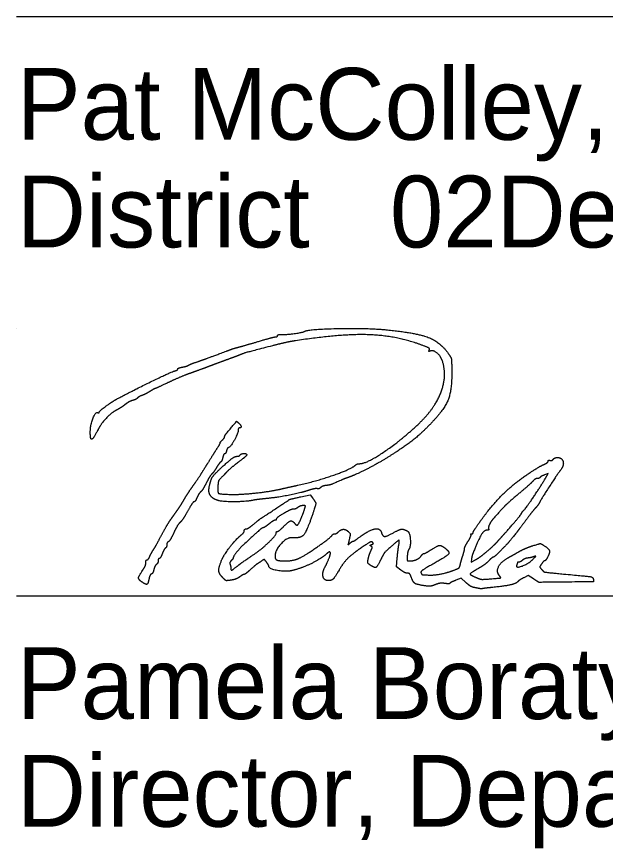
# Model space of a CAD drawing. Extents: x -8.3 to 42.1, y 0 to 22.
# Drawn here: x 24.528 to 25.676, y 7.305 to 8.926 of the extents above; entities that cross this region are included whole.
import ezdxf

# ---------------------------------------------------------------- set-up
doc = ezdxf.new("R2010")
doc.units = 0
doc.layers.add('SH_Data', color=7, linetype='Continuous')
doc.layers.add('SH_Text', color=7, linetype='Continuous')

msp = doc.modelspace()

# ---------------------------------------------------------------- linework, layer by layer
at = {"layer": 'SH_Data'}
for p, q in [((24.5279, 8.9262), (28.0279, 8.9262)), ((24.5279, 8.3191), (24.5279, 8.3191)), ((24.5279, 7.7968), (28.0279, 7.7968))]:
    msp.add_line(p, q, dxfattribs=at)
at = {"layer": 'SH_Text'}
for points in [[(25.5597, 8.0263), (25.5651, 8.0352), (25.5577, 8.0326)], [(25.0824, 7.9901), (25.1004, 7.9942), (25.1051, 7.988)], [(25.2773, 7.8473), (25.269, 7.8536), (25.2704, 7.8707)], [(25.4153, 7.8693), (25.4143, 7.8628), (25.4229, 7.8673)], [(25.5361, 7.83), (25.5255, 7.8368), (25.5171, 7.8323)], [(25.4043, 7.823), (25.3951, 7.8313), (25.3845, 7.8272)]]:
    msp.add_lwpolyline(points, dxfattribs=at)
for points in [[(25.033, 8.3018), (25.0351, 8.3018), (25.0368, 8.3029), (25.0368, 8.3043)], [(25.0368, 8.3043), (25.0368, 8.3056), (25.0408, 8.3066), (25.0458, 8.3065)], [(25.0458, 8.3065), (25.0554, 8.3062), (25.0864, 8.3106), (25.0898, 8.3127)], [(25.3205, 8.285), (25.2699, 8.304), (25.1619, 8.308), (25.0716, 8.2942)], [(25.0898, 8.3127), (25.0966, 8.3169), (25.2136, 8.3192), (25.248, 8.3158)], [(25.248, 8.3158), (25.3072, 8.31), (25.3548, 8.2917), (25.3706, 8.2686)], [(24.9612, 8.282), (24.9665, 8.2833), (24.9839, 8.2883), (25, 8.2931)], [(25, 8.2931), (25.0161, 8.2979), (25.031, 8.3018), (25.033, 8.3018)], [(25.0716, 8.2942), (25.0623, 8.2928), (25.0424, 8.2885), (25.0272, 8.2845)], [(24.8808, 8.2535), (24.8955, 8.2586), (24.9019, 8.261), (24.9372, 8.2741)], [(24.9372, 8.2741), (24.9451, 8.2771), (24.9559, 8.2806), (24.9612, 8.282)], [(25.0272, 8.2845), (24.9762, 8.2714), (24.9719, 8.2701), (24.9612, 8.2658)], [(25.3328, 8.2764), (25.3338, 8.2789), (25.3303, 8.2813), (25.3205, 8.285)], [(25.3352, 8.2743), (25.3326, 8.2733), (25.3319, 8.274), (25.3328, 8.2764)], [(25.3586, 8.2544), (25.3553, 8.2642), (25.3409, 8.2765), (25.3352, 8.2743)], [(24.9384, 8.2573), (24.9285, 8.2537), (24.9134, 8.2481), (24.9048, 8.2449)], [(24.9612, 8.2658), (24.9585, 8.2647), (24.9483, 8.2609), (24.9384, 8.2573)], [(25.3131, 8.1332), (25.344, 8.1627), (25.3679, 8.2262), (25.3586, 8.2544)], [(25.3706, 8.2686), (25.3755, 8.2614), (25.3764, 8.257), (25.3768, 8.2392)], [(24.837, 8.2357), (24.84, 8.2366), (24.8424, 8.2382), (24.8424, 8.2393)], [(24.8424, 8.2393), (24.8424, 8.2403), (24.8464, 8.242), (24.8514, 8.2429)], [(24.8514, 8.2429), (24.8563, 8.2438), (24.8615, 8.2454), (24.8628, 8.2464)], [(24.8628, 8.2464), (24.8641, 8.2473), (24.8722, 8.2506), (24.8808, 8.2535)], [(24.9048, 8.2449), (24.8962, 8.2416), (24.88, 8.2357), (24.8688, 8.2317)], [(25.3768, 8.2392), (25.3775, 8.1984), (25.3614, 8.1587), (25.332, 8.1288)], [(24.7248, 8.1814), (24.755, 8.1976), (24.8286, 8.2333), (24.837, 8.2357)], [(24.8688, 8.2317), (24.8576, 8.2278), (24.8372, 8.2192), (24.8236, 8.2127)], [(24.8236, 8.2127), (24.8099, 8.2063), (24.7983, 8.201), (24.7977, 8.201)], [(24.7877, 8.1953), (24.7828, 8.1922), (24.7761, 8.1888), (24.7729, 8.1878)], [(24.7977, 8.201), (24.7971, 8.201), (24.7927, 8.1984), (24.7877, 8.1953)], [(24.6888, 8.1547), (24.6888, 8.1569), (24.7142, 8.1757), (24.7248, 8.1814)], [(24.754, 8.1778), (24.7505, 8.1769), (24.7438, 8.1733), (24.7392, 8.1697)], [(24.7637, 8.1826), (24.7619, 8.1808), (24.7576, 8.1787), (24.754, 8.1778)], [(24.7729, 8.1878), (24.7697, 8.1868), (24.7655, 8.1844), (24.7637, 8.1826)], [(24.7233, 8.1594), (24.7129, 8.1541), (24.693, 8.1332), (24.6868, 8.1211)], [(24.7392, 8.1697), (24.7346, 8.1661), (24.7274, 8.1615), (24.7233, 8.1594)], [(24.6716, 8.1169), (24.6717, 8.1301), (24.6823, 8.1567), (24.6865, 8.1541)], [(24.6865, 8.1541), (24.6877, 8.1533), (24.6888, 8.1536), (24.6888, 8.1547)], [(24.939, 8.1158), (24.9575, 8.1379), (24.9568, 8.1374), (24.9609, 8.134)], [(24.9609, 8.134), (24.9652, 8.1304), (24.9661, 8.1242), (24.9624, 8.1242)], [(25.1964, 8.0546), (25.2105, 8.0546), (25.2786, 8.1005), (25.3131, 8.1332)], [(25.332, 8.1288), (25.3134, 8.1099), (25.281, 8.085), (25.2505, 8.0662)], [(24.673, 8.1032), (24.6722, 8.104), (24.6716, 8.1101), (24.6716, 8.1169)], [(24.6868, 8.1211), (24.6801, 8.1082), (24.6748, 8.1013), (24.673, 8.1032)], [(24.9336, 8.1072), (24.9336, 8.1084), (24.936, 8.1123), (24.939, 8.1158)], [(24.96, 8.1191), (24.96, 8.1135), (24.9441, 8.0858), (24.9409, 8.0858)], [(24.9624, 8.1242), (24.9611, 8.1242), (24.96, 8.1219), (24.96, 8.1191)], [(24.916, 8.0797), (24.9216, 8.0883), (24.9256, 8.0954), (24.925, 8.0954)], [(24.925, 8.0954), (24.9245, 8.0954), (24.9261, 8.0975), (24.9288, 8.1002)], [(24.9288, 8.1002), (24.9314, 8.1028), (24.9336, 8.1059), (24.9336, 8.1072)], [(24.894, 8.0447), (24.9006, 8.0553), (24.9105, 8.0711), (24.916, 8.0797)], [(24.9374, 8.0798), (24.9366, 8.0765), (24.9349, 8.0738), (24.9337, 8.0738)], [(24.9409, 8.0858), (24.9398, 8.0858), (24.9382, 8.0831), (24.9374, 8.0798)], [(24.9252, 8.0448), (24.9409, 8.0594), (24.9536, 8.069), (24.9576, 8.069)], [(24.93, 8.0666), (24.9291, 8.0626), (24.9274, 8.0588), (24.9261, 8.058)], [(24.9337, 8.0738), (24.9325, 8.0738), (24.9309, 8.0705), (24.93, 8.0666)], [(24.9576, 8.069), (24.9601, 8.069), (24.9628, 8.07), (24.9636, 8.0714)], [(24.9768, 8.0717), (24.9768, 8.0706), (24.97, 8.0647), (24.9618, 8.0586)], [(24.9636, 8.0714), (24.9654, 8.0743), (24.9768, 8.0746), (24.9768, 8.0717)], [(25.2505, 8.0662), (25.2313, 8.0543), (25.1901, 8.0333), (25.176, 8.0282)], [(25.5648, 8.0595), (25.5648, 8.061), (25.5663, 8.0617), (25.5682, 8.061)], [(25.5682, 8.061), (25.5701, 8.0602), (25.5729, 8.0612), (25.5745, 8.0631)], [(25.5745, 8.0631), (25.5761, 8.065), (25.5798, 8.0666), (25.5827, 8.0666)], [(25.5827, 8.0666), (25.5921, 8.0666), (25.5959, 8.0505), (25.5885, 8.0415)], [(24.8722, 8.0117), (24.8776, 8.0192), (24.8874, 8.034), (24.894, 8.0447)], [(24.9038, 8.0102), (24.9066, 8.0232), (24.9127, 8.0332), (24.9252, 8.0448)], [(24.9176, 8.0466), (24.9142, 8.0411), (24.9101, 8.0355), (24.9084, 8.0341)], [(24.9261, 8.058), (24.9248, 8.0572), (24.921, 8.0521), (24.9176, 8.0466)], [(24.9618, 8.0586), (24.9535, 8.0525), (24.941, 8.0416), (24.934, 8.0345)], [(25.0764, 8.0126), (25.1133, 8.0208), (25.1796, 8.0437), (25.1882, 8.0512)], [(25.1882, 8.0512), (25.1903, 8.0531), (25.1939, 8.0546), (25.1964, 8.0546)], [(25.528, 8.0362), (25.5469, 8.0484), (25.5488, 8.0495), (25.557, 8.0532)], [(25.557, 8.0532), (25.5613, 8.0551), (25.5648, 8.058), (25.5648, 8.0595)], [(24.9084, 8.0341), (24.9068, 8.0328), (24.9021, 8.0252), (24.8981, 8.0172)], [(24.934, 8.0345), (24.9233, 8.0235), (24.9211, 8.0199), (24.9206, 8.0116)], [(25.176, 8.0282), (25.1714, 8.0266), (25.1643, 8.0238), (25.1603, 8.022)], [(25.4334, 7.9437), (25.4556, 7.9745), (25.5007, 8.0185), (25.528, 8.0362)], [(25.549, 8.0279), (25.5483, 8.0267), (25.5459, 8.0258), (25.5437, 8.0258)], [(25.5885, 8.0415), (25.5843, 8.0365), (25.5515, 7.9861), (25.5483, 7.9799)], [(25.5577, 8.0326), (25.5537, 8.0312), (25.5498, 8.0291), (25.549, 8.0279)], [(24.8555, 7.9862), (24.8593, 7.9928), (24.8669, 8.0043), (24.8722, 8.0117)], [(24.8981, 8.0172), (24.8941, 8.0092), (24.889, 8.0012), (24.8868, 7.9994)], [(24.9206, 8.0116), (24.9197, 7.9982), (24.9238, 7.9953), (24.9444, 7.9947)], [(25.0428, 8.0051), (25.0507, 8.0069), (25.0658, 8.0103), (25.0764, 8.0126)], [(25.1318, 8.0121), (25.1279, 8.0117), (25.123, 8.0099), (25.121, 8.0081)], [(25.1603, 8.022), (25.1433, 8.0146), (25.1384, 8.0129), (25.1318, 8.0121)], [(25.5349, 8.0204), (25.5322, 8.0174), (25.5197, 8.0063), (25.5072, 7.9958)], [(25.5169, 7.9634), (25.5197, 7.9653), (25.5479, 8.0068), (25.5597, 8.0263)], [(25.5437, 8.0258), (25.5415, 8.0258), (25.5375, 8.0233), (25.5349, 8.0204)], [(24.8868, 7.9994), (24.8847, 7.9976), (24.8814, 7.9925), (24.8796, 7.9881)], [(24.9192, 7.9833), (24.9087, 7.9872), (24.9016, 7.9997), (24.9038, 8.0102)], [(24.9444, 7.9947), (24.9636, 7.9942), (25.0215, 8.0003), (25.0428, 8.0051)], [(25.0962, 8.0022), (25.0797, 7.9969), (25.0346, 7.9884), (25.0108, 7.9861)], [(25.1142, 8.0059), (25.1125, 8.0065), (25.1044, 8.0048), (25.0962, 8.0022)], [(25.121, 8.0081), (25.1189, 8.0063), (25.1158, 8.0053), (25.1142, 8.0059)], [(25.5072, 7.9958), (25.4876, 7.9793), (25.4759, 7.9679), (25.4592, 7.949)], [(24.8425, 7.9655), (24.8458, 7.9703), (24.8517, 7.9796), (24.8555, 7.9862)], [(24.8739, 7.9802), (24.8726, 7.9802), (24.8672, 7.9723), (24.8618, 7.9626)], [(24.8796, 7.9881), (24.8777, 7.9838), (24.8752, 7.9802), (24.8739, 7.9802)], [(24.9904, 7.9835), (24.9767, 7.9804), (24.9272, 7.9803), (24.9192, 7.9833)], [(25.0108, 7.9861), (25.0025, 7.9853), (24.9933, 7.9841), (24.9904, 7.9835)], [(25.0284, 7.9637), (25.06, 7.9847), (25.0614, 7.9854), (25.0824, 7.9901)], [(25.1051, 7.988), (25.1117, 7.9792), (25.1115, 7.9744), (25.1038, 7.9518)], [(25.5483, 7.9799), (25.5466, 7.9764), (25.5427, 7.971), (25.5397, 7.9678)], [(24.8289, 7.9463), (24.833, 7.9521), (24.8391, 7.9608), (24.8425, 7.9655)], [(24.8618, 7.9626), (24.8565, 7.9529), (24.8498, 7.9429), (24.847, 7.9404)], [(24.9892, 7.9358), (25.0029, 7.9468), (25.0009, 7.9455), (25.0284, 7.9637)], [(25.0581, 7.9626), (25.0436, 7.9547), (25.0344, 7.9483), (25.0344, 7.9463)], [(25.0678, 7.9658), (25.0656, 7.9658), (25.0612, 7.9643), (25.0581, 7.9626)], [(25.0765, 7.9693), (25.074, 7.9673), (25.07, 7.9658), (25.0678, 7.9658)], [(25.075, 7.9346), (25.0768, 7.9346), (25.0866, 7.9557), (25.0897, 7.9664)], [(25.0864, 7.9729), (25.0835, 7.9728), (25.0791, 7.9712), (25.0765, 7.9693)], [(25.0897, 7.9664), (25.0914, 7.9721), (25.091, 7.9729), (25.0864, 7.9729)], [(25.513, 7.9582), (25.5142, 7.9604), (25.5159, 7.9627), (25.5169, 7.9634)], [(25.5397, 7.9678), (25.5367, 7.9645), (25.5278, 7.9532), (25.5199, 7.9425)], [(24.81, 7.9142), (24.8163, 7.926), (24.8248, 7.9405), (24.8289, 7.9463)], [(25.0344, 7.9463), (25.0344, 7.9451), (25.0332, 7.9442), (25.0317, 7.9442)], [(25.1038, 7.9518), (25.0935, 7.9219), (25.0815, 7.9088), (25.0656, 7.9102)], [(25.4592, 7.949), (25.4533, 7.9424), (25.4471, 7.9295), (25.4485, 7.9271)], [(25.4817, 7.9204), (25.497, 7.9375), (25.5106, 7.9539), (25.513, 7.9582)], [(24.847, 7.9404), (24.8441, 7.9378), (24.8386, 7.9287), (24.8347, 7.9202)], [(24.9754, 7.9274), (24.9772, 7.9274), (24.9834, 7.9311), (24.9892, 7.9358)], [(25.02, 7.937), (25.015, 7.933), (25.01, 7.9298), (25.0088, 7.9297)], [(25.0317, 7.9442), (25.0303, 7.9442), (25.025, 7.9409), (25.02, 7.937)], [(25.0368, 7.9226), (25.0381, 7.9226), (25.0435, 7.9269), (25.0488, 7.9322)], [(25.0488, 7.9322), (25.0589, 7.9423), (25.0654, 7.9441), (25.0704, 7.9382)], [(25.0704, 7.9382), (25.072, 7.9362), (25.0741, 7.9346), (25.075, 7.9346)], [(25.4184, 7.9203), (25.4184, 7.9217), (25.4251, 7.9322), (25.4334, 7.9437)], [(25.5199, 7.9425), (25.512, 7.9319), (25.5043, 7.9217), (25.5029, 7.9199)], [(24.7946, 7.8866), (24.7968, 7.8899), (24.8037, 7.9023), (24.81, 7.9142)], [(24.8347, 7.9202), (24.8307, 7.9116), (24.826, 7.9037), (24.8242, 7.9026)], [(24.9285, 7.8679), (24.933, 7.8783), (24.9562, 7.9078), (24.9666, 7.9161)], [(24.9666, 7.9161), (24.9695, 7.9185), (24.972, 7.922), (24.972, 7.9239)], [(24.972, 7.9239), (24.972, 7.9258), (24.9735, 7.9274), (24.9754, 7.9274)], [(25.0088, 7.9297), (25.0069, 7.9297), (24.9985, 7.9225), (24.9732, 7.8992)], [(24.9883, 7.876), (25.0039, 7.8864), (25.0344, 7.9151), (25.0344, 7.9194)], [(25.0344, 7.9194), (25.0344, 7.9212), (25.0355, 7.9226), (25.0368, 7.9226)], [(25.1004, 7.8829), (25.119, 7.8953), (25.1414, 7.9119), (25.1431, 7.9147)], [(25.1431, 7.9147), (25.1442, 7.9164), (25.1465, 7.9178), (25.1483, 7.9178)], [(25.1483, 7.9178), (25.1501, 7.9178), (25.1534, 7.9195), (25.1555, 7.9217)], [(25.1555, 7.9217), (25.1605, 7.9266), (25.1705, 7.9267), (25.1754, 7.9217)], [(25.1754, 7.9217), (25.1786, 7.9186), (25.1788, 7.9161), (25.1767, 7.907)], [(25.1935, 7.9091), (25.2138, 7.9243), (25.2365, 7.9299), (25.2395, 7.9204)], [(25.2395, 7.9204), (25.2419, 7.9128), (25.25, 7.9127), (25.2633, 7.9201)], [(25.2633, 7.9201), (25.2752, 7.9267), (25.2825, 7.9274), (25.2907, 7.9228)], [(25.2907, 7.9228), (25.2951, 7.9203), (25.2967, 7.8923), (25.2928, 7.8872)], [(25.4086, 7.9035), (25.4125, 7.9097), (25.415, 7.9155), (25.4142, 7.9163)], [(25.4142, 7.9163), (25.4134, 7.9171), (25.414, 7.9178), (25.4156, 7.9178)], [(25.4156, 7.9178), (25.4171, 7.9178), (25.4184, 7.9189), (25.4184, 7.9203)], [(25.4462, 7.925), (25.4399, 7.925), (25.4304, 7.9098), (25.4183, 7.8806)], [(25.4485, 7.9271), (25.4493, 7.9259), (25.4482, 7.925), (25.4462, 7.925)], [(25.4661, 7.9029), (25.4692, 7.9065), (25.4762, 7.9143), (25.4817, 7.9204)], [(25.5029, 7.9199), (25.4896, 7.9034), (25.485, 7.8983), (25.4732, 7.8861)], [(24.8242, 7.9026), (24.8223, 7.9016), (24.8208, 7.8987), (24.8208, 7.8962)], [(24.9732, 7.8992), (24.9641, 7.8909), (24.9504, 7.8738), (24.9504, 7.8708)], [(25.0656, 7.9102), (25.0552, 7.9111), (25.032, 7.8857), (25.032, 7.8735)], [(25.1767, 7.907), (25.1744, 7.8967), (25.1745, 7.8962), (25.1783, 7.8997)], [(25.1783, 7.8997), (25.1805, 7.9017), (25.1832, 7.9034), (25.1841, 7.9034)], [(25.1841, 7.9034), (25.1851, 7.9034), (25.1893, 7.9059), (25.1935, 7.9091)], [(25.2222, 7.9013), (25.2204, 7.9031), (25.2145, 7.9003), (25.202, 7.8918)], [(25.2206, 7.8971), (25.2236, 7.8982), (25.224, 7.8995), (25.2222, 7.9013)], [(25.2734, 7.8956), (25.2752, 7.905), (25.2726, 7.9054), (25.2633, 7.8972)], [(25.4016, 7.8887), (25.4016, 7.8905), (25.4047, 7.8972), (25.4086, 7.9035)], [(25.446, 7.8841), (25.4539, 7.8909), (25.4629, 7.8994), (25.4661, 7.9029)], [(25.5353, 7.8948), (25.5493, 7.899), (25.5505, 7.899), (25.5564, 7.8952)], [(24.7877, 7.874), (24.7893, 7.8776), (24.7924, 7.8833), (24.7946, 7.8866)], [(24.8183, 7.8901), (24.8169, 7.8892), (24.8141, 7.8843), (24.812, 7.8792)], [(24.8208, 7.8962), (24.8208, 7.8937), (24.8197, 7.8909), (24.8183, 7.8901)], [(25.0519, 7.865), (25.065, 7.865), (25.0841, 7.872), (25.1004, 7.8829)], [(25.14, 7.8797), (25.14, 7.8827), (25.136, 7.8822), (25.1324, 7.8787)], [(25.202, 7.8918), (25.1823, 7.8784), (25.1651, 7.8613), (25.1568, 7.847)], [(25.2136, 7.8682), (25.2144, 7.8723), (25.2166, 7.8794), (25.2187, 7.8838)], [(25.2194, 7.8936), (25.2172, 7.895), (25.2175, 7.8959), (25.2206, 7.8971)], [(25.2187, 7.8838), (25.2215, 7.8901), (25.2217, 7.8922), (25.2194, 7.8936)], [(25.2633, 7.8972), (25.2474, 7.8832), (25.2437, 7.8788), (25.2382, 7.8674)], [(25.2704, 7.8707), (25.2712, 7.8801), (25.2726, 7.8913), (25.2734, 7.8956)], [(25.2928, 7.8872), (25.2916, 7.8855), (25.2903, 7.8798), (25.2899, 7.8746)], [(25.3224, 7.8794), (25.3236, 7.8794), (25.3297, 7.8826), (25.336, 7.8866)], [(25.3642, 7.8895), (25.3739, 7.8819), (25.367, 7.874), (25.3354, 7.8563)], [(25.336, 7.8866), (25.3489, 7.8948), (25.3565, 7.8956), (25.3642, 7.8895)], [(25.3981, 7.8746), (25.4, 7.8805), (25.4016, 7.8869), (25.4016, 7.8887)], [(25.4229, 7.8673), (25.4277, 7.8697), (25.4381, 7.8773), (25.446, 7.8841)], [(25.4732, 7.8861), (25.4657, 7.8784), (25.4586, 7.8722), (25.4576, 7.8722)], [(25.4864, 7.8711), (25.4893, 7.8726), (25.4981, 7.8776), (25.506, 7.8821)], [(25.506, 7.8821), (25.5139, 7.8866), (25.5271, 7.8923), (25.5353, 7.8948)], [(25.5564, 7.8952), (25.566, 7.8889), (25.5684, 7.8815), (25.5638, 7.8725)], [(24.78, 7.8617), (24.78, 7.8648), (24.7811, 7.8674), (24.7824, 7.8674)], [(24.7824, 7.8674), (24.7838, 7.8674), (24.7862, 7.8703), (24.7877, 7.874)], [(24.804, 7.8653), (24.804, 7.8628), (24.8024, 7.8595), (24.8005, 7.8579)], [(24.8061, 7.8698), (24.8049, 7.8698), (24.804, 7.8677), (24.804, 7.8653)], [(24.812, 7.8792), (24.81, 7.874), (24.8073, 7.8698), (24.8061, 7.8698)], [(24.9302, 7.8322), (24.9225, 7.8398), (24.9219, 7.8526), (24.9285, 7.8679)], [(24.9466, 7.8657), (24.9446, 7.8636), (24.9435, 7.8604), (24.9442, 7.8585)], [(24.9504, 7.8708), (24.9504, 7.87), (24.9487, 7.8677), (24.9466, 7.8657)], [(24.9568, 7.8536), (24.9643, 7.8597), (24.9696, 7.8635), (24.9883, 7.876)], [(25.0154, 7.8624), (25.0109, 7.8682), (25.0108, 7.8682), (25.0041, 7.8638)], [(25.032, 7.8735), (25.032, 7.8683), (25.0398, 7.865), (25.0519, 7.865)], [(25.1324, 7.8787), (25.1228, 7.8696), (25.084, 7.8508), (25.0656, 7.8463)], [(25.1294, 7.853), (25.1335, 7.8606), (25.14, 7.8769), (25.14, 7.8797)], [(25.2182, 7.8566), (25.2132, 7.8599), (25.2124, 7.8619), (25.2136, 7.8682)], [(25.2382, 7.8674), (25.2315, 7.8537), (25.2267, 7.8511), (25.2182, 7.8566)], [(25.2899, 7.8746), (25.2894, 7.867), (25.2901, 7.865), (25.2932, 7.865)], [(25.2932, 7.865), (25.3016, 7.865), (25.3136, 7.8698), (25.3168, 7.8745)], [(25.3168, 7.8745), (25.3187, 7.8772), (25.3212, 7.8794), (25.3224, 7.8794)], [(25.3933, 7.8575), (25.394, 7.8609), (25.3961, 7.8686), (25.3981, 7.8746)], [(25.4183, 7.8806), (25.4172, 7.8779), (25.4159, 7.8728), (25.4153, 7.8693)], [(25.449, 7.8652), (25.4454, 7.8614), (25.4373, 7.8553), (25.431, 7.8516)], [(25.4576, 7.8722), (25.4565, 7.8722), (25.4526, 7.869), (25.449, 7.8652)], [(25.4694, 7.8367), (25.4633, 7.8441), (25.4731, 7.8639), (25.4864, 7.8711)], [(25.5033, 7.8568), (25.5008, 7.8503), (25.5263, 7.8593), (25.5348, 7.8679)], [(25.5144, 7.8662), (25.5122, 7.8642), (25.5091, 7.8626), (25.5076, 7.8626)], [(25.5254, 7.8707), (25.5215, 7.8702), (25.5166, 7.8681), (25.5144, 7.8662)], [(25.5372, 7.8734), (25.5345, 7.8724), (25.5292, 7.8712), (25.5254, 7.8707)], [(25.5348, 7.8679), (25.5403, 7.8735), (25.5408, 7.8748), (25.5372, 7.8734)], [(25.5638, 7.8725), (25.5616, 7.8683), (25.5589, 7.865), (25.5578, 7.865)], [(24.7742, 7.8475), (24.7774, 7.8522), (24.78, 7.8586), (24.78, 7.8617)], [(24.8005, 7.8579), (24.7986, 7.8563), (24.7964, 7.8518), (24.7955, 7.8478)], [(24.9442, 7.8585), (24.945, 7.8565), (24.9456, 7.8534), (24.9456, 7.8516)], [(24.9456, 7.8516), (24.9456, 7.8467), (24.949, 7.8473), (24.9568, 7.8536)], [(25.0041, 7.8638), (24.9959, 7.8584), (24.9933, 7.8564), (24.9821, 7.8464)], [(25.0199, 7.855), (25.0199, 7.8559), (25.0179, 7.8592), (25.0154, 7.8624)], [(25.0656, 7.8463), (25.0527, 7.8433), (25.0201, 7.8494), (25.0199, 7.855)], [(25.1361, 7.8266), (25.1277, 7.8266), (25.1237, 7.8424), (25.1294, 7.853)], [(25.3354, 7.8563), (25.3222, 7.8488), (25.316, 7.844), (25.3168, 7.8418)], [(25.3806, 7.8469), (25.3894, 7.8502), (25.3923, 7.8527), (25.3933, 7.8575)], [(25.431, 7.8516), (25.4131, 7.8412), (25.412, 7.8379), (25.425, 7.8324)], [(25.5048, 7.8616), (25.5048, 7.861), (25.5041, 7.8589), (25.5033, 7.8568)], [(25.5076, 7.8626), (25.506, 7.8626), (25.5048, 7.8621), (25.5048, 7.8616)], [(25.5519, 7.8591), (25.5484, 7.8538), (25.5484, 7.8529), (25.5523, 7.8482)], [(25.5578, 7.865), (25.5567, 7.865), (25.554, 7.8623), (25.5519, 7.8591)], [(24.7725, 7.8238), (24.7655, 7.8286), (24.7659, 7.8354), (24.7742, 7.8475)], [(24.7908, 7.8394), (24.7891, 7.8388), (24.787, 7.8346), (24.7862, 7.8302)], [(24.7955, 7.8478), (24.7946, 7.8439), (24.7925, 7.8401), (24.7908, 7.8394)], [(24.9629, 7.8338), (24.9593, 7.8312), (24.9519, 7.8284), (24.9464, 7.8276)], [(24.9714, 7.8386), (24.9703, 7.8386), (24.9665, 7.8364), (24.9629, 7.8338)], [(24.9821, 7.8464), (24.9773, 7.8421), (24.9725, 7.8386), (24.9714, 7.8386)], [(25.1568, 7.847), (25.1486, 7.8329), (25.1422, 7.8266), (25.1361, 7.8266)], [(25.2903, 7.841), (25.2877, 7.841), (25.2819, 7.8438), (25.2773, 7.8473)], [(25.2978, 7.8332), (25.296, 7.8383), (25.2934, 7.841), (25.2903, 7.841)], [(25.3232, 7.8166), (25.3082, 7.819), (25.3013, 7.8235), (25.2978, 7.8332)], [(25.3168, 7.8418), (25.3181, 7.8384), (25.3188, 7.8382), (25.3308, 7.8375)], [(25.3308, 7.8375), (25.3413, 7.8369), (25.3674, 7.8418), (25.3806, 7.8469)], [(25.4518, 7.8299), (25.4713, 7.8315), (25.4731, 7.8322), (25.4694, 7.8367)], [(25.5523, 7.8482), (25.5559, 7.8437), (25.5609, 7.8427), (25.5948, 7.8395)], [(25.5948, 7.8395), (25.6439, 7.835), (25.6521, 7.8334), (25.6531, 7.8287)], [(24.7862, 7.8302), (24.7843, 7.8205), (24.7801, 7.8185), (24.7725, 7.8238)], [(24.9464, 7.8276), (24.9377, 7.8262), (24.9355, 7.8268), (24.9302, 7.8322)], [(25.3443, 7.8186), (25.3373, 7.8158), (25.3318, 7.8153), (25.3232, 7.8166)], [(25.3632, 7.8211), (25.3574, 7.8219), (25.3501, 7.8209), (25.3443, 7.8186)], [(25.3733, 7.8215), (25.3729, 7.8206), (25.3683, 7.8204), (25.3632, 7.8211)], [(25.3845, 7.8272), (25.3787, 7.8249), (25.3737, 7.8224), (25.3733, 7.8215)], [(25.4189, 7.8135), (25.4159, 7.8142), (25.4093, 7.8184), (25.4043, 7.823)], [(25.425, 7.8324), (25.4318, 7.8294), (25.4383, 7.8289), (25.4518, 7.8299)], [(25.5054, 7.8244), (25.5017, 7.8207), (25.4802, 7.8158), (25.4568, 7.8134)], [(25.5171, 7.8323), (25.5125, 7.8298), (25.5072, 7.8263), (25.5054, 7.8244)], [(25.5828, 7.8236), (25.5471, 7.8232), (25.5467, 7.8232), (25.5361, 7.83)], [(25.6531, 7.8287), (25.6539, 7.8244), (25.6519, 7.8243), (25.5828, 7.8236)], [(25.4292, 7.8114), (25.4265, 7.8119), (25.4219, 7.8129), (25.4189, 7.8135)], [(25.4376, 7.8111), (25.4356, 7.8107), (25.4318, 7.8108), (25.4292, 7.8114)], [(25.4568, 7.8134), (25.4482, 7.8125), (25.4396, 7.8115), (25.4376, 7.8111)]]:
    msp.add_open_spline(points, degree=2, dxfattribs=at)

# ---------------------------------------------------------------- texts
for s, p in [('Pat McColley, P.E., S.I.', (24.5279, 8.6862)), ('District       Deputy Director', (24.5279, 8.4762)), ('              02', (24.5279, 8.4762)), ('Pamela Boratyn', (24.5279, 7.5568)), ('Director, Department of Transportation', (24.5279, 7.3468))]:
    msp.add_text(s, height=0.14, dxfattribs=at).set_placement(p)

doc.saveas('drawing.dxf')
